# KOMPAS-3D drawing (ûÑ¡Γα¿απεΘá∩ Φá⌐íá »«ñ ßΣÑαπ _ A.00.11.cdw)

Views: Сверху 1, Сверху, Изометрия XYZ 2, Изометрия XYZ, Разрез А-А
Referenced files in C:\Users\s.slezkin\Desktop\Чертежи ЗНП\Раскатчик арок 2\: Центрирующая шайба под сферу _ A.00.11.m3d, Центрирующая шайба под сферу _ A.00.11.cdw
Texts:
  Центрирующая шайба под сферу
  http://vk.com/sergey_krd
  Центрирующая
  шайба под сферу
Dimensions and other numbers on the sheet: 28; 25,3; 13; 3,74; 12; 2:1; 1; 0,03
